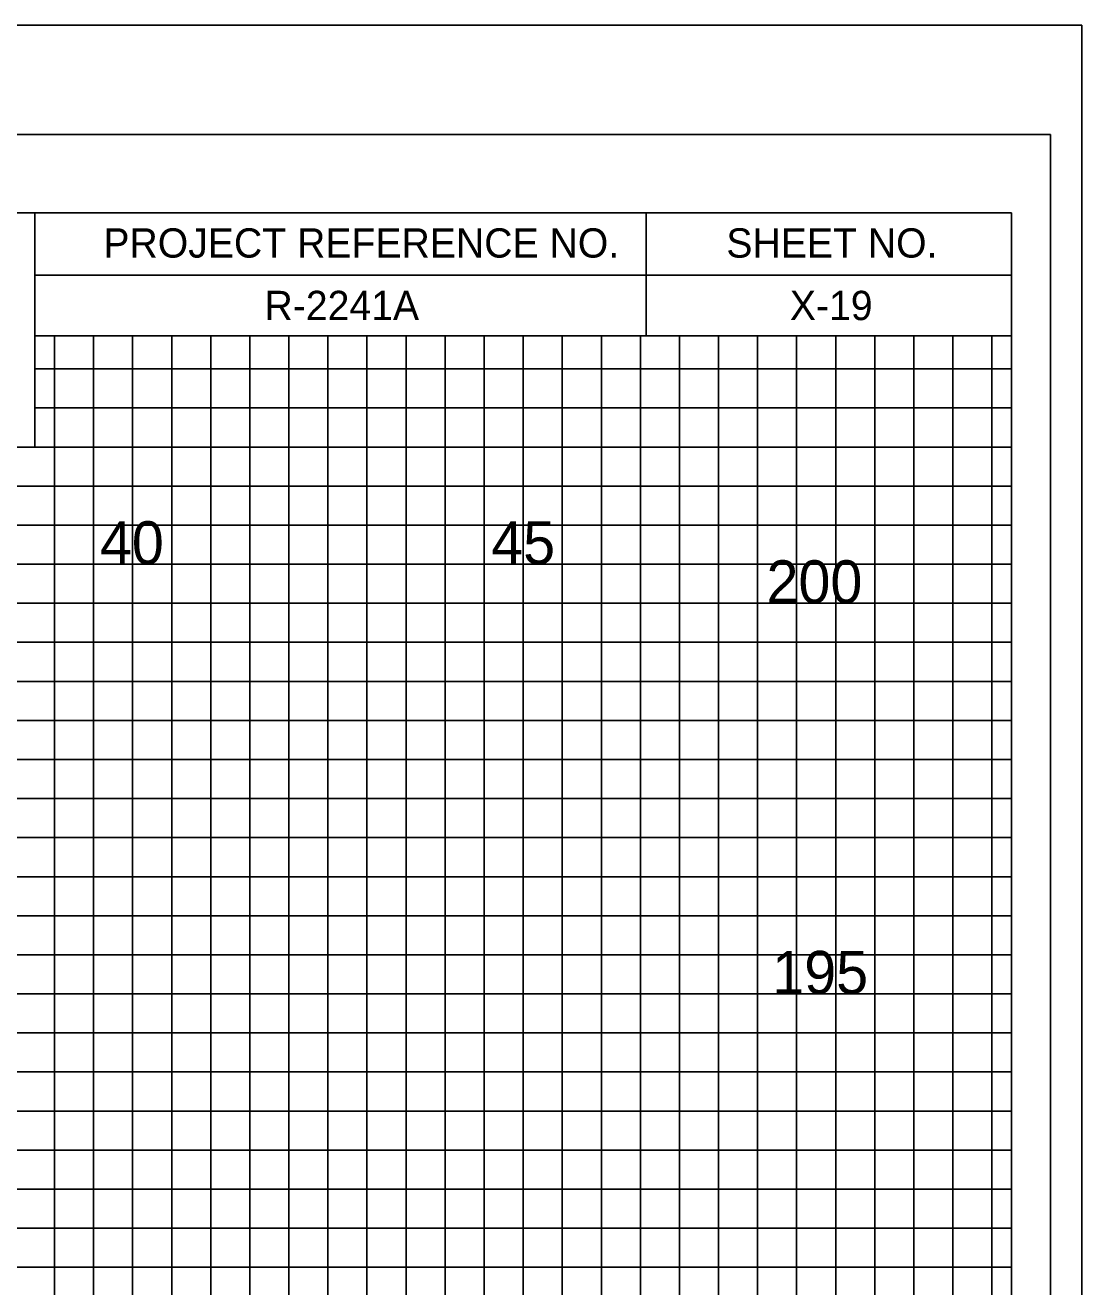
# Model space of a CAD drawing. Extents: x -4 to 103, y -2 to 6583.
# Drawn here: x 89.88 to 103.4, y 1326.1 to 1342.25 of the extents above; entities that cross this region are included whole.
import ezdxf

# ---------------------------------------------------------------- set-up
doc = ezdxf.new("R2010")
doc.units = 0
for name, color, linetype in [('Prop XS Elevation Labels', 7, 'Continuous'), ('Prop XS Offset Labels', 7, 'Continuous'), ('Prop XS Project Number', 7, 'Continuous'), ('Prop XS Sheet Number', 7, 'Continuous'), ('Sheet Cross Section CELL', 7, 'Continuous'), ('Sheet Cross Section Grid Major CELL', 7, 'Continuous'), ('Sheet Cross Section Grid Middle CELL', 7, 'Continuous'), ('Sheet Cutting Line CELL', 7, 'Continuous'), ('Sheet DOT Grid CELL', 7, 'Continuous'), ('Sheet Plot Border Inside CELL', 7, 'Continuous'), ('Sheet Plot Border Outside CELL', 7, 'Continuous')]:
    doc.layers.add(name, color=color, linetype=linetype)

msp = doc.modelspace()

# ---------------------------------------------------------------- linework, layer by layer
at = {"layer": 'Sheet Cross Section CELL'}
for p, q in [((90, 1339.85), (102.5, 1339.85)), ((90, 1339.85), (102.5, 1339.85)), ((97.825, 1338.275), (97.825, 1339.85)), ((101.875, 1339.85), (101.875, 1339.85)), ((102.5, 1339.85), (102.5, 1339.85)), ((102.5, 1338.275), (102.5, 1339.85)), ((102.5, 1339.85), (102.5, 1339.85)), ((102.5, 1339.85), (102.5, 1339.85)), ((102.5, 1338.275), (102.5, 1339.85)), ((90, 1339.05), (102.5, 1339.05)), ((90, 1338.275), (102.5, 1338.275)), ((99.4, 1338.275), (99.4, 1338.275)), ((99.4, 1338.275), (99.4, 1338.275))]:
    msp.add_line(p, q, dxfattribs=at)
for points in [[(102.5, 1339.85), (0, 1339.85), (0, 1274.85), (102.5, 1274.85)], [(83.75, 1339.85), (90, 1339.85), (90, 1336.85), (83.75, 1336.85)]]:
    msp.add_lwpolyline(points, close=True, dxfattribs=at)
at = {"layer": 'Sheet Cross Section Grid Major CELL'}
for points in [[(91.25, 1274.85), (91.25, 1338.275), (93.75, 1338.275), (93.75, 1274.85)], [(96.25, 1274.85), (96.25, 1338.275), (98.75, 1338.275), (98.75, 1274.85)], [(101.25, 1274.85), (101.25, 1338.275)], [(90, 1337.35), (102.5, 1337.35)], [(0, 1332.35), (102.5, 1332.35), (102.5, 1334.85), (0, 1334.85)], [(0, 1327.35), (102.5, 1327.35), (102.5, 1329.85), (0, 1329.85)]]:
    msp.add_lwpolyline(points, dxfattribs=at)
at = {"layer": 'Sheet Cross Section Grid Middle CELL'}
for points in [[(90.25, 1274.85), (90.25, 1338.275), (90.75, 1338.275), (90.75, 1274.85)], [(91.75, 1274.85), (91.75, 1338.275), (92.25, 1338.275), (92.25, 1274.85)], [(92.75, 1274.85), (92.75, 1338.275), (93.25, 1338.275), (93.25, 1274.85)], [(94.25, 1274.85), (94.25, 1338.275), (94.75, 1338.275), (94.75, 1274.85)], [(95.25, 1274.85), (95.25, 1338.275), (95.75, 1338.275), (95.75, 1274.85)], [(96.75, 1274.85), (96.75, 1338.275), (97.25, 1338.275), (97.25, 1274.85)], [(97.75, 1274.85), (97.75, 1338.275), (98.25, 1338.275), (98.25, 1274.85)], [(99.25, 1274.85), (99.25, 1338.275), (99.75, 1338.275), (99.75, 1274.85)], [(100.25, 1274.85), (100.25, 1338.275)], [(100.25, 1338.275), (100.75, 1338.275), (100.75, 1274.85), (101.75, 1274.85), (101.75, 1338.275), (102.25, 1338.275), (102.25, 1274.85)], [(102.5, 1336.85), (102.5, 1337.85), (90, 1337.85)], [(0, 1336.35), (102.5, 1336.35), (102.5, 1336.85), (0, 1336.85)], [(0, 1335.35), (102.5, 1335.35), (102.5, 1335.85), (0, 1335.85)], [(0, 1333.85), (102.5, 1333.85), (102.5, 1334.35), (0, 1334.35)], [(0, 1332.85), (102.5, 1332.85), (102.5, 1333.35), (0, 1333.35)], [(0, 1331.35), (102.5, 1331.35), (102.5, 1331.85), (0, 1331.85)], [(0, 1330.35), (102.5, 1330.35), (102.5, 1330.85), (0, 1330.85)], [(0, 1328.85), (102.5, 1328.85), (102.5, 1329.35), (0, 1329.35)], [(0, 1327.85), (102.5, 1327.85), (102.5, 1328.35), (0, 1328.35)], [(0, 1326.35), (102.5, 1326.35), (102.5, 1326.85), (0, 1326.85)]]:
    msp.add_lwpolyline(points, dxfattribs=at)
at = {"layer": 'Sheet Cutting Line CELL'}
msp.add_line((-3.5, 1342.25), (103.4, 1342.25), dxfattribs=at)
at = {"layer": 'Sheet DOT Grid CELL'}
for p, q in [((91.25, 1274.85), (91.25, 1338.275)), ((93.75, 1274.85), (93.75, 1338.275)), ((96.25, 1274.85), (96.25, 1338.275)), ((98.75, 1274.85), (98.75, 1338.275)), ((101.25, 1274.85), (101.25, 1338.275)), ((90, 1337.35), (102.5, 1337.35)), ((0, 1334.85), (102.5, 1334.85)), ((0, 1332.35), (102.5, 1332.35)), ((0, 1329.85), (102.5, 1329.85)), ((0, 1327.35), (102.5, 1327.35))]:
    msp.add_line(p, q, dxfattribs=at)
at = {"layer": 'Sheet Plot Border Inside CELL'}
msp.add_lwpolyline([(103, 1340.85), (-2.8, 1340.85), (-2.8, 1273.85), (103, 1273.85)], close=True, dxfattribs=at)
at = {"layer": 'Sheet Plot Border Outside CELL'}
msp.add_lwpolyline([(103.4, 1342.25), (-3.5, 1342.25), (-3.5, 1272.425), (103.4, 1272.425)], close=True, dxfattribs=at)

# ---------------------------------------------------------------- texts
at = {"layer": 'Prop XS Elevation Labels'}
for s, p in [('200', (99.364, 1334.85)), ('195', (99.438, 1329.85))]:
    msp.add_text(s, height=0.55, dxfattribs=at).set_placement(p)
at = {"layer": 'Prop XS Offset Labels'}
for s, p in [('40', (90.831, 1335.35)), ('45', (95.84, 1335.35))]:
    msp.add_text(s, height=0.55, dxfattribs=at).set_placement(p)
at = {"layer": 'Prop XS Project Number'}
msp.add_text('R-2241A', height=0.375, dxfattribs=at).set_placement((92.938, 1338.475))
at = {"layer": 'Prop XS Sheet Number'}
msp.add_text('X-19', height=0.375, dxfattribs=at).set_placement((99.663, 1338.475))
at = {"layer": 'Sheet Cross Section CELL'}
for s, p in [('PROJECT REFERENCE NO.', (90.875, 1339.275)), ('SHEET NO.', (98.85, 1339.275))]:
    msp.add_text(s, height=0.375, dxfattribs=at).set_placement(p)

doc.saveas('drawing.dxf')
